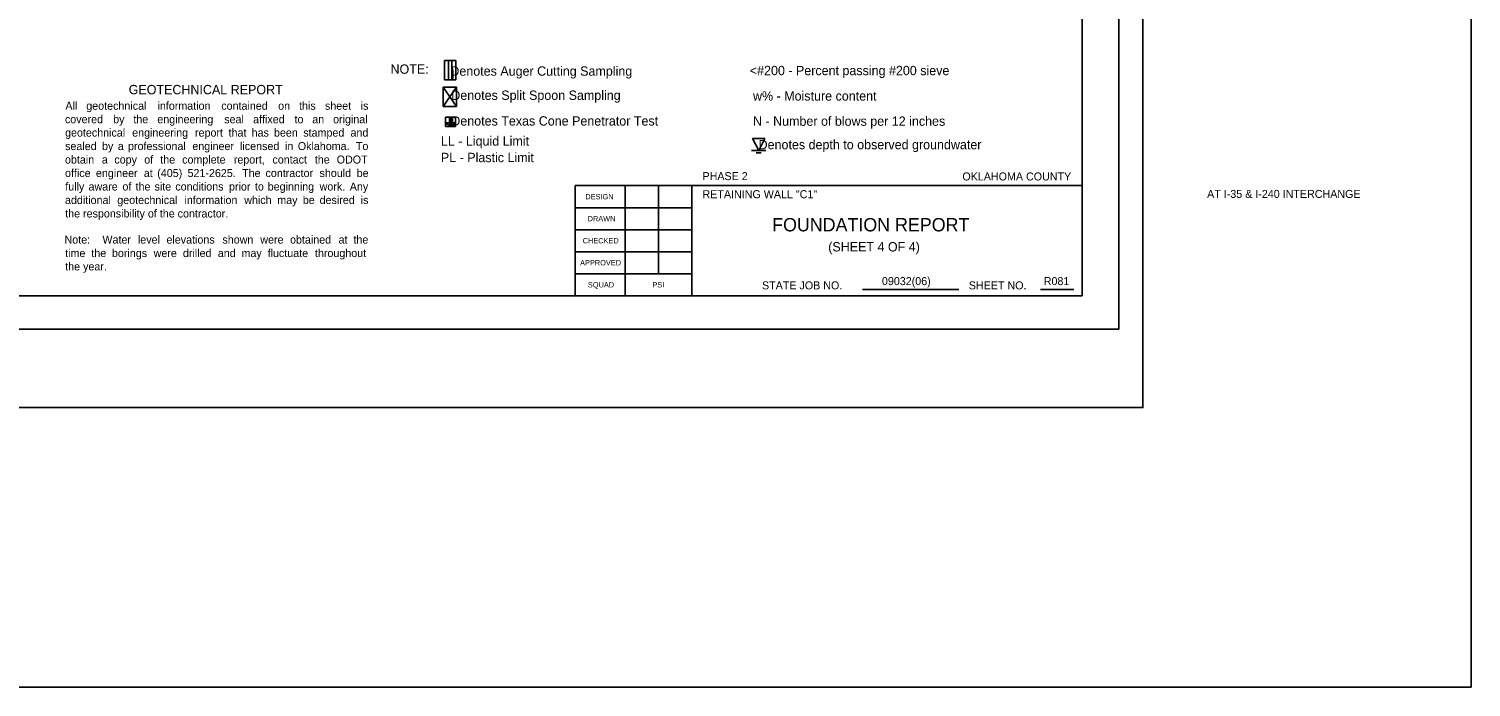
# Model space of a CAD drawing. Extents: x -6 to 173, y 24 to 64.
# Drawn here: x 150.95 to 172.58, y 25.78 to 35.65 of the extents above; entities that cross this region are included whole.
import ezdxf

# ---------------------------------------------------------------- set-up
doc = ezdxf.new("R2010")
doc.units = 0
for name, color, linetype in [('4', 7, 'Continuous'), ('S', 7, 'Continuous'), ('SHT_Plot_Shape_Full', 7, 'Continuous'), ('SHT_Plot_Shape_Half', 7, 'Continuous'), ('SHT_Sheet_Border', 7, 'Continuous'), ('SHT_Standard_Sheet_Lines', 7, 'Continuous'), ('SHT_Standard_Sheet_Txt', 7, 'Continuous'), ('T', 7, 'Continuous'), ('T-5', 7, 'Continuous'), ('Text', 7, 'Continuous')]:
    doc.layers.add(name, color=color, linetype=linetype)

# ---------------------------------------------------------------- blocks, each defined once
blk = doc.blocks.new('DGRFC_WTLEV1_1')
for points in [[(-0.005, 0), (0.005, 0)], [(0, 0), (0.0042, 0.0083), (-0.0042, 0.0083), (0, 0)], [(-0.0017, -0.0017), (0.0017, -0.0017)]]:
    blk.add_lwpolyline(points)

msp = doc.modelspace()

# ---------------------------------------------------------------- linework, layer by layer
msp.add_line((157.187, 35.172), (157.187, 34.881))
for points in [[(157.187, 35.172), (157.354, 35.172)], [(157.354, 34.881), (157.354, 35.172)], [(157.187, 34.881), (157.354, 34.881)], [(157.187, 34.881), (157.354, 34.881)]]:
    msp.add_lwpolyline(points)
for points in [[(157.245, 35.172), (157.245, 34.881), (157.295, 34.881), (157.295, 35.172)], [(157.31, 35.005), (157.304, 35.047), (157.295, 35.087), (157.31, 35.005)], [(157.295, 35.087), (157.295, 34.881), (157.31, 35.005), (157.295, 35.087)], [(157.295, 34.881), (157.31, 34.922), (157.31, 35.005), (157.295, 34.881)], [(157.295, 34.881), (157.304, 34.881), (157.31, 34.922), (157.295, 34.881)], [(157.31, 34.922), (157.312, 34.963), (157.31, 35.005), (157.31, 34.922)]]:
    msp.add_lwpolyline(points, close=True)
at = {"layer": 'S'}
msp.add_lwpolyline([(-6.024, 64.421), (172.576, 64.421), (172.576, 25.783), (-6.024, 25.783)], close=True, dxfattribs=at)
at = {"layer": 'SHT_Plot_Shape_Full'}
msp.add_lwpolyline([(131.656, 53.971), (167.656, 53.971), (167.656, 29.971), (131.656, 29.971)], close=True, dxfattribs=at)
at = {"layer": 'SHT_Plot_Shape_Half'}
msp.add_lwpolyline([(133.294, 53.146), (167.294, 53.146), (167.294, 31.146), (133.294, 31.146)], close=True, dxfattribs=at)
at = {"layer": 'SHT_Sheet_Border'}
for p, q in [((159.144, 31.646), (159.144, 33.296)), ((159.144, 33.296), (166.744, 33.296)), ((160.894, 31.646), (160.894, 33.297))]:
    msp.add_line(p, q, dxfattribs=at)
msp.add_lwpolyline([(135.244, 52.646), (166.744, 52.646), (166.744, 31.646), (135.244, 31.646)], close=True, dxfattribs=at)
at = {"layer": 'SHT_Standard_Sheet_Lines'}
for p, q in [((159.894, 31.646), (159.894, 33.297)), ((160.394, 31.976), (160.394, 33.297)), ((163.454, 31.742), (164.895, 31.742)), ((166.119, 31.742), (166.622, 31.742))]:
    msp.add_line(p, q, dxfattribs=at)
for points in [[(160.894, 32.966), (159.144, 32.966)], [(160.894, 32.636), (159.144, 32.636)], [(160.894, 32.306), (159.144, 32.306)], [(160.894, 31.976), (159.144, 31.976)]]:
    msp.add_lwpolyline(points, dxfattribs=at)
at = {"layer": 'Text'}
for p, q in [((157.163, 34.481), (157.163, 34.773)), ((157.199, 34.181), (157.199, 34.322))]:
    msp.add_line(p, q, dxfattribs=at)
for points in [[(157.163, 34.481), (157.363, 34.773)], [(157.163, 34.773), (157.363, 34.481)], [(157.163, 34.773), (157.363, 34.773)], [(157.363, 34.481), (157.363, 34.773)], [(157.163, 34.481), (157.363, 34.481)], [(157.199, 34.322), (157.349, 34.322)], [(157.199, 34.181), (157.349, 34.181)], [(157.349, 34.181), (157.349, 34.322)]]:
    msp.add_lwpolyline(points, dxfattribs=at)
for points in [[(157.259, 34.237), (157.199, 34.237), (157.274, 34.181), (157.259, 34.237)], [(157.259, 34.237), (157.289, 34.322), (157.259, 34.322), (157.259, 34.237)], [(157.259, 34.237), (157.289, 34.237), (157.289, 34.322), (157.259, 34.237)], [(157.259, 34.237), (157.274, 34.181), (157.289, 34.237), (157.259, 34.237)], [(157.274, 34.181), (157.349, 34.237), (157.289, 34.237), (157.274, 34.181)]]:
    msp.add_lwpolyline(points, close=True, dxfattribs=at)

# ---------------------------------------------------------------- block references
at = {"layer": 'Text', "xscale": 21.6, "yscale": 21.6}
msp.add_blockref('DGRFC_WTLEV1_1', (161.895, 33.823), dxfattribs=at)

# ---------------------------------------------------------------- texts
at = {"layer": '4'}
msp.add_text('FOUNDATION REPORT', height=0.2, dxfattribs=at).set_placement((162.097, 32.611))
at = {"layer": 'SHT_Standard_Sheet_Txt'}
for s, height, p in [('DESIGN', 0.08, (159.296, 33.091)), ('DRAWN', 0.08, (159.331, 32.761)), ('CHECKED', 0.08, (159.257, 32.431)), ('APPROVED', 0.08, (159.218, 32.101)), ('SQUAD', 0.08, (159.335, 31.771)), ('PSI', 0.08, (160.302, 31.771)), ('STATE JOB NO.', 0.12, (161.945, 31.742)), ('SHEET NO. ', 0.12, (165.045, 31.742))]:
    msp.add_text(s, height=height, dxfattribs=at).set_placement(p)
at = {"layer": 'T'}
for s, p in [('PHASE 2', (161.053, 33.379)), ('OKLAHOMA COUNTY', (164.949, 33.374)), ('RETAINING WALL "C1" ', (161.053, 33.108)), ('AT I-35 & I-240 INTERCHANGE', (168.618, 33.112)), ('09032(06)', (163.743, 31.806)), ('R081', (166.169, 31.806))]:
    msp.add_text(s, height=0.12, dxfattribs=at).set_placement(p)
at = {"layer": 'T-5'}
msp.add_text('(SHEET 4 OF 4)', height=0.14, dxfattribs=at).set_placement((162.938, 32.31))
at = {"layer": 'Text'}
for s, height, p in [('NOTE:', 0.14, (156.376, 34.972)), ('    Denotes Auger Cutting Sampling', 0.14, (157.065, 34.943)), (' <#200 - Percent passing #200 sieve', 0.14, (161.71, 34.951)), ('GEOTECHNICAL REPORT', 0.14, (152.451, 34.665)), ('    Denotes Split Spoon Sampling', 0.14, (157.079, 34.581)), ('w% - Moisture content', 0.14, (161.81, 34.57)), ('All', 0.12, (151.502, 34.433)), ('geotechnical', 0.12, (151.815, 34.433)), ('information', 0.12, (152.883, 34.433)), ('contained', 0.12, (153.839, 34.433)), ('on', 0.12, (154.692, 34.433)), ('this', 0.12, (155.005, 34.433)), ('sheet', 0.12, (155.393, 34.433)), ('is ', 0.12, (155.929, 34.433)), ('covered', 0.12, (151.495, 34.231)), ('by', 0.12, (152.218, 34.231)), ('the', 0.12, (152.521, 34.231)), ('engineering', 0.12, (152.88, 34.231)), ('seal', 0.12, (153.883, 34.231)), ('affixed', 0.12, (154.316, 34.231)), ('to', 0.12, (154.937, 34.231)), ('an', 0.12, (155.203, 34.231)), ('original ', 0.12, (155.515, 34.231)), ('    Denotes Texas Cone Penetrator Test', 0.14, (157.079, 34.196)), ('N - Number of blows per 12 inches', 0.14, (161.81, 34.193)), ('sealed', 0.12, (151.497, 33.829)), ('geotechnical', 0.12, (151.497, 34.031)), ('by', 0.12, (152.051, 33.829)), ('professional', 0.12, (152.441, 33.829)), ('engineering', 0.12, (152.503, 34.031)), ('engineer', 0.12, (153.405, 33.829)), ('report', 0.12, (153.445, 34.031)), ('that', 0.12, (153.948, 34.031)), ('licensed', 0.12, (154.12, 33.829)), ('has', 0.12, (154.294, 34.031)), ('been', 0.12, (154.629, 34.031)), ('in', 0.12, (154.795, 33.829)), ('Oklahoma.', 0.12, (154.986, 33.829)), ('stamped', 0.12, (155.068, 34.031)), ('and ', 0.12, (155.776, 34.031)), ('To ', 0.12, (155.857, 33.829)), (' LL - Liquid Limit', 0.14, (157.079, 33.895)), ('    Denotes depth to observed groundwater', 0.14, (161.686, 33.841)), ('obtain', 0.12, (151.496, 33.627)), ('a', 0.12, (152.288, 33.829)), ('of', 0.12, (152.684, 33.627)), ('the', 0.12, (152.924, 33.627)), ('complete', 0.12, (153.252, 33.627)), ('report,', 0.12, (154.027, 33.627)), ('contact', 0.12, (154.606, 33.627)), ('the', 0.12, (155.241, 33.627)), ('ODOT ', 0.12, (155.569, 33.627)), (' PL - Plastic Limit', 0.14, (157.079, 33.648)), ('office', 0.12, (151.496, 33.425)), ('engineer', 0.12, (151.96, 33.425)), ('a', 0.12, (152.048, 33.627)), ('copy', 0.12, (152.236, 33.627)), ('at', 0.12, (152.677, 33.425)), ('(405)', 0.12, (152.879, 33.425)), ('521-2625.', 0.12, (153.333, 33.425)), ('The', 0.12, (154.151, 33.425)), ('contractor', 0.12, (154.502, 33.425)), ('should', 0.12, (155.312, 33.425)), ('be ', 0.12, (155.869, 33.425)), ('fully', 0.12, (151.5, 33.223)), ('aware', 0.12, (151.849, 33.223)), ('of', 0.12, (152.357, 33.223)), ('the', 0.12, (152.554, 33.223)), ('site', 0.12, (152.838, 33.223)), ('conditions', 0.12, (153.15, 33.223)), ('prior', 0.12, (153.955, 33.223)), ('to', 0.12, (154.344, 33.223)), ('beginning', 0.12, (154.535, 33.223)), ('work.', 0.12, (155.313, 33.223)), ('Any ', 0.12, (155.765, 33.223)), ('additional', 0.12, (151.496, 33.021)), ('geotechnical', 0.12, (152.28, 33.021)), ('information', 0.12, (153.287, 33.021)), ('which', 0.12, (154.183, 33.021)), ('may', 0.12, (154.678, 33.021)), ('be', 0.12, (155.061, 33.021)), ('desired', 0.12, (155.313, 33.021)), ('is ', 0.12, (155.929, 33.021)), ('the responsibility of the contractor.', 0.12, (151.499, 32.819)), ('Note:', 0.12, (151.489, 32.428)), ('Water', 0.12, (152.057, 32.428)), ('level', 0.12, (152.589, 32.428)), ('elevations', 0.12, (153.017, 32.428)), ('shown', 0.12, (153.856, 32.428)), ('were', 0.12, (154.424, 32.428)), ('obtained', 0.12, (154.87, 32.428)), ('at', 0.12, (155.597, 32.428)), ('the ', 0.12, (155.82, 32.428)), ('time', 0.12, (151.499, 32.226)), ('the', 0.12, (151.891, 32.226)), ('borings', 0.12, (152.2, 32.226)), ('were', 0.12, (152.825, 32.226)), ('drilled', 0.12, (153.264, 32.226)), ('and', 0.12, (153.787, 32.226)), ('may', 0.12, (154.142, 32.226)), ('fluctuate', 0.12, (154.534, 32.226)), ('throughout ', 0.12, (155.243, 32.226)), ('the year.', 0.12, (151.499, 32.026))]:
    msp.add_text(s, height=height, dxfattribs=at).set_placement(p)

doc.saveas('drawing.dxf')
